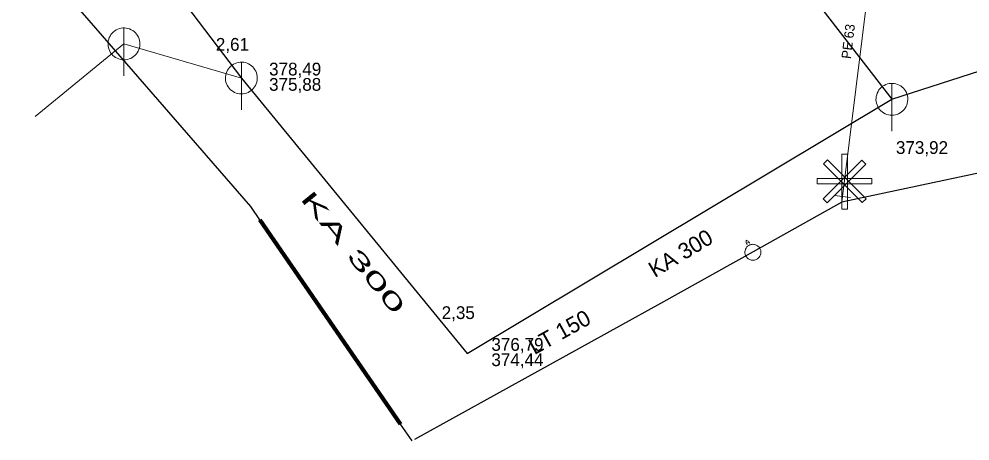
# Model space of a CAD drawing. Extents: x -809028 to -807737, y -990545 to -989489.
# Drawn here: x -807927.8 to -807868.1, y -990263.7 to -990237.2 of the extents above; entities that cross this region are included whole.
import ezdxf

# ---------------------------------------------------------------- set-up
doc = ezdxf.new("R2010")
doc.units = 0
doc.header["$LTSCALE"] = 0.32
for name, color, linetype, lineweight in [('1', 7, 'Continuous', 13), ('11', 7, 'Continuous', 13), ('12', 7, 'Continuous', 13), ('13', 7, 'Continuous', 13), ('14', 7, 'Continuous', 25), ('17', 7, 'Continuous', 25), ('22', 7, 'Continuous', 13), ('23', 7, 'Continuous', 13), ('3', 7, 'Continuous', 106), ('34', 7, 'Continuous', 13)]:
    doc.layers.add(name, color=color, linetype=linetype, lineweight=lineweight)

msp = doc.modelspace()

# ---------------------------------------------------------------- linework, layer by layer
at = {"layer": '11'}
msp.add_lwpolyline([(-807926.802, -990243.369), (-807921.222, -990238.806), (-807913.853, -990240.947)], dxfattribs=at)
at = {"layer": '12'}
for points in [[(-807874.899, -990246.093), (-807874.651, -990246.341), (-807877.08, -990248.77), (-807877.326, -990248.522)], [(-807877.318, -990246.332), (-807877.071, -990246.084), (-807874.642, -990248.513), (-807874.889, -990248.761)], [(-807876.165, -990245.729), (-807875.815, -990245.729), (-807875.815, -990249.164), (-807876.165, -990249.164)], [(-807874.281, -990247.238), (-807874.281, -990247.588), (-807877.716, -990247.588), (-807877.716, -990247.238)]]:
    msp.add_lwpolyline(points, close=True, dxfattribs=at)
at = {"layer": '13'}
msp.add_lwpolyline([(-807876.162, -990248.738), (-807876.125, -990248.37), (-807873.622, -990228.333)], dxfattribs=at)
at = {"layer": '14'}
for p, q in [((-807929.141, -990220.804), (-807913.853, -990240.947)), ((-807913.853, -990240.947), (-807899.68, -990258.21)), ((-807899.68, -990258.21), (-807873.019, -990242.278))]:
    msp.add_line(p, q, dxfattribs=at)
msp.add_lwpolyline([(-807898.791, -990212.317), (-807881.1, -990231.838), (-807873.019, -990242.278), (-807856.393, -990236.921)], dxfattribs=at)
at = {"layer": '17'}
for points in [[(-807748.636, -990145.472), (-807738.068, -990149.112), (-807736.999, -990150.649), (-807744.916, -990175.098), (-807753.434, -990201.463), (-807760.305, -990223.25), (-807761.118, -990224.188), (-807763.195, -990224.671), (-807781.931, -990228.704), (-807782.135, -990228.77), (-807804.256, -990233.43), (-807804.384, -990233.462), (-807840.221, -990241.099), (-807876.162, -990248.738), (-807881.735, -990251.842)], [(-807903.127, -990263.702), (-807903.857, -990262.642), (-807912.682, -990249.831), (-807913.265, -990248.997), (-807933.984, -990225.173), (-807955.859, -990200.033), (-807965.127, -990190.002), (-807971.857, -990183.267)], [(-807881.735, -990251.842), (-807887.541, -990255.078), (-807902.977, -990263.62)]]:
    msp.add_lwpolyline(points, dxfattribs=at)
at = {"layer": '22'}
for p, q in [((-807921.222, -990240.806), (-807921.221, -990237.806)), ((-807913.853, -990242.947), (-807913.852, -990239.947)), ((-807873.019, -990244.279), (-807873.018, -990241.279))]:
    msp.add_line(p, q, dxfattribs=at)
for points in [[(-807920.222, -990238.806), (-807920.227, -990238.697), (-807920.245, -990238.589), (-807920.275, -990238.483), (-807920.315, -990238.382), (-807920.367, -990238.285), (-807920.429, -990238.195), (-807920.501, -990238.112), (-807920.581, -990238.038), (-807920.669, -990237.972), (-807920.763, -990237.917), (-807920.863, -990237.872), (-807920.968, -990237.839), (-807921.075, -990237.817), (-807921.184, -990237.807), (-807921.294, -990237.809), (-807921.402, -990237.823), (-807921.509, -990237.848), (-807921.612, -990237.885), (-807921.71, -990237.934), (-807921.802, -990237.992), (-807921.888, -990238.061), (-807921.965, -990238.138), (-807922.034, -990238.224), (-807922.093, -990238.316), (-807922.141, -990238.414), (-807922.178, -990238.517), (-807922.204, -990238.624), (-807922.218, -990238.732), (-807922.221, -990238.842), (-807922.211, -990238.951), (-807922.19, -990239.058), (-807922.156, -990239.162), (-807922.112, -990239.262), (-807922.057, -990239.357), (-807921.991, -990239.445), (-807921.917, -990239.525), (-807921.834, -990239.597), (-807921.744, -990239.659), (-807921.648, -990239.711), (-807921.546, -990239.752), (-807921.441, -990239.782), (-807921.333, -990239.8), (-807921.223, -990239.806), (-807921.114, -990239.8), (-807921.006, -990239.782), (-807920.901, -990239.753), (-807920.799, -990239.712), (-807920.702, -990239.66), (-807920.612, -990239.598), (-807920.529, -990239.527), (-807920.454, -990239.447), (-807920.389, -990239.359), (-807920.333, -990239.265), (-807920.289, -990239.165), (-807920.255, -990239.061), (-807920.233, -990238.953), (-807920.223, -990238.844)], [(-807912.853, -990240.947), (-807912.858, -990240.838), (-807912.876, -990240.73), (-807912.906, -990240.624), (-807912.946, -990240.523), (-807912.998, -990240.426), (-807913.06, -990240.336), (-807913.132, -990240.253), (-807913.212, -990240.179), (-807913.3, -990240.113), (-807913.394, -990240.058), (-807913.494, -990240.013), (-807913.599, -990239.98), (-807913.706, -990239.958), (-807913.815, -990239.948), (-807913.925, -990239.95), (-807914.033, -990239.964), (-807914.14, -990239.989), (-807914.243, -990240.026), (-807914.341, -990240.075), (-807914.433, -990240.133), (-807914.519, -990240.202), (-807914.596, -990240.279), (-807914.665, -990240.365), (-807914.724, -990240.457), (-807914.772, -990240.555), (-807914.809, -990240.658), (-807914.835, -990240.765), (-807914.849, -990240.873), (-807914.852, -990240.983), (-807914.842, -990241.092), (-807914.821, -990241.199), (-807914.787, -990241.303), (-807914.743, -990241.403), (-807914.688, -990241.498), (-807914.622, -990241.586), (-807914.548, -990241.666), (-807914.465, -990241.738), (-807914.375, -990241.8), (-807914.279, -990241.852), (-807914.177, -990241.893), (-807914.072, -990241.923), (-807913.964, -990241.941), (-807913.854, -990241.947), (-807913.745, -990241.941), (-807913.637, -990241.923), (-807913.532, -990241.894), (-807913.43, -990241.853), (-807913.333, -990241.801), (-807913.243, -990241.739), (-807913.16, -990241.668), (-807913.085, -990241.588), (-807913.02, -990241.5), (-807912.964, -990241.406), (-807912.92, -990241.306), (-807912.886, -990241.202), (-807912.864, -990241.094), (-807912.854, -990240.985)], [(-807872.019, -990242.279), (-807872.024, -990242.17), (-807872.042, -990242.062), (-807872.072, -990241.956), (-807872.112, -990241.855), (-807872.164, -990241.758), (-807872.226, -990241.668), (-807872.298, -990241.585), (-807872.378, -990241.511), (-807872.466, -990241.445), (-807872.56, -990241.39), (-807872.66, -990241.345), (-807872.765, -990241.312), (-807872.872, -990241.29), (-807872.981, -990241.28), (-807873.091, -990241.282), (-807873.199, -990241.296), (-807873.306, -990241.321), (-807873.409, -990241.358), (-807873.507, -990241.407), (-807873.599, -990241.465), (-807873.685, -990241.534), (-807873.762, -990241.611), (-807873.831, -990241.697), (-807873.89, -990241.789), (-807873.938, -990241.887), (-807873.975, -990241.99), (-807874.001, -990242.097), (-807874.015, -990242.205), (-807874.018, -990242.315), (-807874.008, -990242.424), (-807873.987, -990242.531), (-807873.953, -990242.635), (-807873.909, -990242.735), (-807873.854, -990242.83), (-807873.788, -990242.918), (-807873.714, -990242.998), (-807873.631, -990243.07), (-807873.541, -990243.132), (-807873.445, -990243.184), (-807873.343, -990243.225), (-807873.238, -990243.255), (-807873.13, -990243.273), (-807873.02, -990243.279), (-807872.911, -990243.273), (-807872.803, -990243.255), (-807872.698, -990243.226), (-807872.596, -990243.185), (-807872.499, -990243.133), (-807872.409, -990243.071), (-807872.326, -990243), (-807872.251, -990242.92), (-807872.186, -990242.832), (-807872.13, -990242.738), (-807872.086, -990242.638), (-807872.052, -990242.534), (-807872.03, -990242.426), (-807872.02, -990242.317)]]:
    msp.add_lwpolyline(points, close=True, dxfattribs=at)
at = {"layer": '23'}
msp.add_line((-807881.975, -990251.234), (-807882.146, -990251.329), dxfattribs=at)
for points in [[(-807881.309, -990251.625), (-807881.338, -990251.58), (-807881.371, -990251.539), (-807881.408, -990251.503), (-807881.448, -990251.47), (-807881.492, -990251.441), (-807881.539, -990251.417), (-807881.588, -990251.398), (-807881.637, -990251.385), (-807881.689, -990251.376), (-807881.741, -990251.373), (-807881.794, -990251.375), (-807881.847, -990251.384), (-807881.897, -990251.397), (-807881.944, -990251.415), (-807881.991, -990251.438), (-807882.037, -990251.468), (-807882.076, -990251.499), (-807882.115, -990251.538), (-807882.147, -990251.576), (-807882.176, -990251.62), (-807882.2, -990251.668), (-807882.218, -990251.717), (-807882.232, -990251.768), (-807882.242, -990251.819), (-807882.244, -990251.871), (-807882.24, -990251.924), (-807882.233, -990251.974), (-807882.219, -990252.025), (-807882.2, -990252.074), (-807882.178, -990252.121), (-807882.15, -990252.165), (-807882.116, -990252.206), (-807882.079, -990252.244), (-807882.039, -990252.276), (-807881.996, -990252.304), (-807881.949, -990252.328), (-807881.9, -990252.348), (-807881.849, -990252.361), (-807881.798, -990252.369)], [(-807882.115, -990251.538), (-807882.147, -990251.576), (-807882.176, -990251.62), (-807882.2, -990251.668), (-807882.218, -990251.717), (-807882.232, -990251.768), (-807882.242, -990251.819), (-807882.244, -990251.871), (-807882.24, -990251.924), (-807882.233, -990251.974), (-807882.219, -990252.025), (-807882.2, -990252.074), (-807882.178, -990252.121), (-807882.15, -990252.165), (-807882.116, -990252.206), (-807882.079, -990252.244), (-807882.039, -990252.276), (-807881.996, -990252.304), (-807881.949, -990252.328), (-807881.9, -990252.348), (-807881.849, -990252.361), (-807881.798, -990252.369), (-807881.746, -990252.373), (-807881.693, -990252.37), (-807881.642, -990252.363), (-807881.591, -990252.348), (-807881.543, -990252.329), (-807881.496, -990252.307), (-807881.452, -990252.278), (-807881.411, -990252.246), (-807881.373, -990252.209), (-807881.341, -990252.168), (-807881.312, -990252.124), (-807881.288, -990252.078), (-807881.27, -990252.028), (-807881.255, -990251.979), (-807881.247, -990251.928), (-807881.244, -990251.874), (-807881.246, -990251.822), (-807881.254, -990251.77)], [(-807882.099, -990251.414), (-807882.171, -990251.284), (-807882.158, -990251.104), (-807882, -990251.189), (-807881.927, -990251.319)], [(-807881.798, -990252.369), (-807881.746, -990252.373), (-807881.693, -990252.37), (-807881.642, -990252.363), (-807881.591, -990252.348), (-807881.543, -990252.329), (-807881.496, -990252.307), (-807881.452, -990252.278), (-807881.411, -990252.246), (-807881.373, -990252.209), (-807881.341, -990252.168), (-807881.312, -990252.124), (-807881.288, -990252.078), (-807881.27, -990252.028), (-807881.255, -990251.979), (-807881.247, -990251.928), (-807881.244, -990251.874), (-807881.246, -990251.822), (-807881.254, -990251.77), (-807881.269, -990251.72), (-807881.287, -990251.672), (-807881.309, -990251.625), (-807881.338, -990251.58), (-807881.371, -990251.539), (-807881.408, -990251.503), (-807881.448, -990251.47), (-807881.492, -990251.441), (-807881.539, -990251.417), (-807881.588, -990251.398), (-807881.637, -990251.385), (-807881.689, -990251.376), (-807881.741, -990251.373), (-807881.794, -990251.375), (-807881.847, -990251.384), (-807881.897, -990251.397), (-807881.944, -990251.415), (-807881.991, -990251.438), (-807882.037, -990251.468), (-807882.076, -990251.499), (-807882.115, -990251.538)], [(-807881.254, -990251.77), (-807881.269, -990251.72), (-807881.287, -990251.672), (-807881.309, -990251.625)]]:
    msp.add_lwpolyline(points, dxfattribs=at)
at = {"layer": '3'}
msp.add_line((-807903.858, -990262.642), (-807912.683, -990249.832), dxfattribs=at)
at = {"layer": '3', "lineweight": 100}
msp.add_line((-807903.858, -990262.642), (-807912.683, -990249.832), dxfattribs=at)
at = {"layer": '34'}
msp.add_line((-807876.621, -990248.308), (-807875.628, -990248.432), dxfattribs=at)

# ---------------------------------------------------------------- texts
at = {"layer": '1'}
for s, height, rotation, p in [('PE 63 ', 0.6, 83, (-807875.597, -990239.772)), ('KA 300', 1, 31, (-807887.905, -990253.487)), ('LT 150', 1, 29, (-807895.457, -990258.323))]:
    msp.add_text(s, height=height, rotation=rotation, dxfattribs=at).set_placement(p)
for s, p in [('2,61', (-807915.453, -990239.235)), ('2,35', (-807901.279, -990256.057))]:
    msp.add_text(s, height=0.8, dxfattribs=at).set_placement(p)
at = {"layer": '1', "width": 2.15}
msp.add_text('KA 300', height=1, rotation=309, dxfattribs=at).set_placement((-807910.204, -990248.518))
at = {"layer": '14'}
for s, p in [('378,49', (-807912.11, -990240.786)), ('375,88', (-807912.11, -990241.746)), ('373,92', (-807872.767, -990245.705)), ('376,79', (-807898.158, -990258.05)), ('374,44', (-807898.158, -990259.01))]:
    msp.add_text(s, height=0.8, dxfattribs=at).set_placement(p)

doc.saveas('drawing.dxf')
